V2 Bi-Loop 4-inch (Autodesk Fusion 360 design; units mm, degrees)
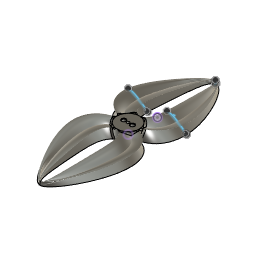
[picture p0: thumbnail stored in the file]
sketch "Hub 5mm Shaft" plane through (0, 0, 0) normal (0, 0, 1) x axis (1, 0, 0)
  circle C1 centre (0, 0) radius 6.5
  circle C2 centre (0, 0) radius 2.5
  point P1 (0, 0)
  point P2 (0, 0)
  point P3 (0, 0)
  coincident P1 P2
  coincident P1 P3
  dimension "d1" diameter C1 = 13
  dimension "d2" diameter C2 = 5
extrude "Extrude1" new body sketch "Hub 5mm Shaft" along normal blind 6 bodies "Hub 5mm Shaft"
sketch "Start Profile" plane through (0, 0, 0) normal (1, 0, 0) x axis (0, 1, 0)
  line L1 (-0.9, 0) -> (0, 0)
  line L2 (-5, 0) -> (-5.9, 0)
  curve K1 (-5, 0) -> (-5.9, 0)
  curve K2 (0, 0) -> (-0.9, 0)
  curve K3 (6.3, 6) -> (5.7, 6)
  curve K4 (0.3, 6) -> (-0.3, 6)
  curve K5 (-1, -1.5) -> (1, 1.5)
  curve K6 (-6, -1.5) -> (-4, 1.5)
  curve K7 (-4.9, 1.5) -> (-6.9, -1.5)
  curve K8 (0.1, 1.5) -> (-1.9, -1.5)
  point P1 (0, 0)
  point P2 (0, 0)
  point P6 (0, 0)
  point P3 (6, 6)
  point P4 (0, 6)
  point P8 (-5, 0)
  point P5 (-5.9, 0)
  point P7 (-0.9, 0)
  point P9 (5.7, 6)
  point P10 (6.3, 6)
  point P11 (-0.3, 6)
  point P12 (0.3, 6)
  point P21 (0, 0)
  point P24 (0, 0)
  coincident P1 P2
  coincident P1 P6
  horizontal L1
  horizontal L2
  midpoint P3 K3
  midpoint P4 K4
  midpoint P2 K5
  midpoint P8 K6
  midpoint P5 K7
  midpoint P7 K8
  dimension "d5" distance P2 P7 = 0.9
  dimension "d6" distance P5 P8 = 0.9
  dimension "d7" distance P2 P8 = 5
  dimension "d8" distance P4 P5 = 5.9
  dimension "d9" distance P2 P4 = 6
  dimension "d10" distance P2 P3 = 6
  dimension "d11" distance P2 P3 = 6
  dimension "d12" distance P9 P10 = 0.6
  dimension "d13" distance P11 P12 = 0.6
  dimension "d17" distance P21 = 50.8 (= "( ( 101.6 ) / 2 ) * 1 mm")
  dimension "d38" distance P24 = 16.9333 (= "( 101.6 / 3 / 2 ) * 1 mm")
  dimension "d46" distance P24 = 16.9333 (= "( 101.6 / 2 / 3 ) * 1 mm")
sketch "Edge Profile" plane through (0, 0, 0) normal (1, 0, 0) x axis (0, 1, 0)
  line L1 (50, 0) -> (50.8, 0)
  curve K1 (50, 0) -> (50.8, 0)
  curve K2 (50.8, 1) -> (50.8, -1)
  curve K3 (50, -1) -> (50, 1)
  curve K4 (50.1, 2) -> (50.6, 2)
  point P2 (50.8, 0)
  point P3 (50, 0)
  point P4 (50.35, 2)
  point P9 (0, 0)
  point P10 (50.6, 2)
  point P11 (50.1, 2)
  horizontal L1
  midpoint P2 K2
  midpoint P3 K3
  midpoint P4 K4
  dimension "d14" distance P2 P3 = 0.8
  dimension "d15" distance P2 P4 = 2
  dimension "d16" distance P2 P4 = 0.45
  dimension "d17" distance P2 P9 = 50.8 (= "( ( 101.6 ) / 2 ) * 1 mm")
  dimension "d18" distance P10 P11 = 0.5
sketch "Target Rail" plane through (0, 0, 0) normal (0, 0, 1) x axis (1, 0, 0)
  line L1 (0, -0.9) -> (0, 0)
  line L2 (0, 21.1667) -> (0, 0)
  line L3 (21.1667, 21.1667) -> (0, 21.1667)
  line L4 (-21.1667, 21.1667) -> (0, 21.1667)
  circle C1 centre (0, 0) radius 63.5
  point P1 (0, 0)
  point P2 (0, 0)
  point P5 (0, 0)
  point P6 (0, 21.1667)
  point P7 (21.1667, 21.1667)
  point P8 (-21.1667, 21.1667)
  coincident P1 P2
  coincident P1 P5
  parallel L1 L2
  perpendicular L2 L3
  perpendicular L2 L4
  dimension "d19" diameter C1 = 127
  dimension "d20" distance P5 P6 = 21.1667 (= "( ( 127 / 2 ) / 3 ) * 1 mm")
  dimension "d21" distance P6 P7 = 21.1667 (= "( ( 127 / 2 ) / 3 ) * 1 mm")
  dimension "d22" distance P6 P8 = 21.1667 (= "( 127 / 2 / 3 ) * 1 mm")
work_plane "WorkPlane1" AlongDistance 16.9333 (= "( 101.6 / 2 / 3 ) * 1 mm")
sketch "Mid Profile" plane through (0, 16.9333, 0) normal (0, 1, 0) x axis (1, 0, 0)
  curve K1 (16.0333, 0) -> (16.9333, 0)
  curve K2 (14.2667, -2) -> (19.6, 2)
  curve K3 (5.1333, -6) -> (5.7333, -6)
  curve K4 (18.9, 2) -> (13.1667, -2)
  line L1 (16.0333, 0) -> (16.9333, 0)
  line L2 (5.1333, -6) -> (5.7333, -6)
  line L3 (-6.3333, 0) -> (-5.4333, 0)
  curve K5 (-6.3333, 0) -> (-5.4333, 0)
  curve K6 (-8.1, -2) -> (-2.7667, 2)
  curve K7 (-17.2333, -6) -> (-16.6333, -6)
  curve K8 (-3.4667, 2) -> (-9.2, -2)
  point P2 (0, 0)
  point P5 (16.9333, 0)
  point P7 (5.4333, -6)
  point P3 (5.7333, -6)
  point P4 (5.1333, -6)
  point P14 (-16.9333, -6)
  point P17 (-5.4333, 0)
  point P13 (-16.6333, -6)
  point P18 (-17.2333, -6)
  point P19 (-6.3333, 0)
  point P8 (16.0333, 0)
  dimension "d38" distance P2 P5 = 16.9333 (= "( 101.6 / 3 / 2 ) * 1 mm")
  dimension "d39" distance P5 P7 = 11.5
  dimension "d40" distance P5 P7 = 6
  dimension "d41" distance P3 P4 = 0.6
  dimension "d42" distance P14 P17 = 11.5
  dimension "d43" distance P14 P17 = 6
  dimension "d44" distance P13 P18 = 0.6
  dimension "d46" distance P2 P14 = 16.9333 (= "( 101.6 / 2 / 3 ) * 1 mm")
  dimension "d47" distance P17 P19 = 0.9
  dimension "d84" distance P5 P8 = 0.9
sketch "End Profile" plane through (0, 0, 0) normal (1, 0, 0) x axis (0, 1, 0)
  line L1 (5, 0) -> (5.8, 0)
  curve K1 (0, 0) -> (0.8, 0)
  curve K2 (-0.2, 1.5) -> (1.8, -1.5)
  curve K3 (-6.25, 6) -> (-5.75, 6)
  curve K4 (1, -1.5) -> (-1, 1.5)
  line L2 (0.8, 0) -> (0, 0)
  curve K5 (5, 0) -> (5.8, 0)
  curve K6 (4.8, 1.5) -> (6.8, -1.5)
  curve K7 (-0.25, 6) -> (0.35, 6)
  curve K8 (6, -1.5) -> (4, 1.5)
  line L3 (-6.25, 6) -> (-5.75, 6)
  line L4 (-0.25, 6) -> (0.35, 6)
  point P2 (0, 0)
  point P11 (0.8, 0)
  point P14 (5, 0)
  point P20 (5.8, 0)
  point P5 (0, 0)
  point P6 (0, 6)
  point P12 (0, 0)
  point P18 (-6, 6)
  point P7 (-6.25, 6)
  point P23 (-5.75, 6)
  point P3 (0.35, 6)
  point P17 (-0.25, 6)
  dimension "d57" distance P2 P11 = 0.8
  dimension "d58" distance P14 P20 = 0.8
  dimension "d59" distance P5 P20 = 5.8
  dimension "d60" distance P6 P12 = 6
  dimension "d61" distance P6 P20 = 5.8
  dimension "d62" distance P11 P18 = 6.8
  dimension "d63" distance P2 P7 = 6
  dimension "d65" distance P7 P23 = 0.5
  dimension "d66" distance P3 P17 = 0.6
  dimension "d67" distance P6 P17 = 0.25
sketch "Lower Rails" plane through (0, 0, 0) normal (0, 0, 1) x axis (1, 0, 0)
  curve K1 (0, 5) -> (0, -0.9)
  curve K2 (0, 0) -> (0, 5.8)
  curve K3 (-9, 0) -> (9, 0)
  curve K4 (9, -1.1) -> (-9, -0.7)
  curve K5 (-3, 5.8) -> (3, 5.8)
  curve K6 (3, 5) -> (-3, 5)
  curve K7 (-5.5871, 26.9005) -> (-5.2796, 6.9661)
  curve K8 (-6.1796, 6.9661) -> (-6.4871, 26.9005)
  curve K9 (-2.5, 50.8) -> (2.5, 50.8)
  curve K10 (2.2, 50) -> (-2.2, 50)
  point P2 (0, -0.9)
  point P7 (0, -0.9)
  point P3 (16.9333, 16.9333)
  point P8 (16.9333, 16.9333)
  point P4 (0, 50.8)
  point P9 (0, 50.8)
  point P5 (-6.3333, 16.9333)
  point P10 (-6.3333, 16.9333)
  point P11 (0, 5.8)
  point P16 (0, 5.8)
  point P12 (-5.4333, 16.9333)
  point P17 (-5.4333, 16.9333)
  point P13 (0, 50)
  point P18 (0, 50)
  point P14 (16.0333, 16.9333)
  point P19 (16.0333, 16.9333)
  point P1 (0, 0)
  point P15 (0, 0)
  point P6 (0, 5)
  coincident P2 P7
  coincident P3 P8
  coincident P4 P9
  coincident P5 P10
  coincident P11 P16
  coincident P12 P17
  coincident P13 P18
  coincident P14 P19
  coincident P1 P15
  midpoint P15 K3
  midpoint P2 K4
  midpoint P11 K5
  midpoint P6 K6
  midpoint P12 K7
  midpoint P5 K8
  parallel K7 K8
  midpoint P4 K9
  midpoint P13 K10
work_plane "WorkPlane2" AlongDistance 6
sketch "Upper Rails" plane through (0, 0, 6) normal (0, 0, 1) x axis (1, 0, 0)
  curve K1 (0, 0) -> (0, 6)
  curve K2 (9.5, -0.3) -> (-9.5, 0.3)
  curve K3 (3, 6) -> (-3, 6)
  curve K4 (5.4985, 26.7287) -> (5.3682, 7.138)
  curve K5 (-17.3406, 8.5207) -> (-16.5261, 25.3459)
  curve K6 (-1.8, 50.35) -> (1.8, 50.35)
  point P2 (0, 6)
  point P7 (0, 6)
  point P3 (5.4333, 16.9333)
  point P8 (5.4333, 16.9333)
  point P5 (-16.9333, 16.9333)
  point P10 (-16.9333, 16.9333)
  point P6 (0, 0)
  point P4 (0, 50.35)
  coincident P2 P7
  coincident P3 P8
  coincident P5 P10
  midpoint P6 K2
  midpoint P2 K3
  midpoint P3 K4
  midpoint P5 K5
  midpoint P4 K6
loft "Loft1" sketch "Start Profile" + "Mid Profile" + "Edge Profile" bodies "Template 1 4x2.5x2"
loft "Loft2" sketch "Edge Profile" + "Mid Profile" + "End Profile"
circular_pattern "C-Pattern1" TotalAngle 360 bodies "Template 2 4x2.5x2"
sketch "Blade Trimmer" plane through (0, 0, 0) normal (0, 0, 1) x axis (1, 0, 0)
  circle C1 centre (0, 0) radius 3
  point P1 (0, 0)
  point P2 (0, 0)
  coincident P1 P2
  dimension "d71" diameter C1 = 6
extrude "Extrude2" cut sketch "Blade Trimmer" along normal blind 14
copy_paste_bodies "CopyPasteBodies1"
chamfer "Start Profile" distance 0.5
offset_faces "OffsetFaces1" distance 2
combine "Start Profile"
fillet "Fillet1" radius 1
offset_faces "OffsetFaces2" distance -2
sketch "Fillet Trimmer" plane through (0, 0, 6) normal (0, 0, 1) x axis (-1, 0, 0)
  arc A1 centre (0, 0) radius 6.5 clockwise from (6.5, -0.0086) to (5.4558, -3.5333)
  arc A2 centre (0, 0) radius 6.5 clockwise from (0.6602, 6.4664) to (4.9682, 4.1913)
  arc A3 centre (0, 0) radius 6.5 clockwise from (-6.5, 0.0086) to (-5.4558, 3.5333)
  arc A4 centre (0, 0) radius 6.5 clockwise from (-4.9682, -4.1913) to (-6.5, 0.0086)
  arc A5 centre (0, 0) radius 6.5 clockwise from (-0.6602, -6.4664) to (-4.9682, -4.1913)
  arc A6 centre (0, 0) radius 6.5 clockwise from (5.4558, -3.5333) to (-0.6602, -6.4664)
  circle C1 centre (0, 0) radius 3
  circle C2 centre (0, 0) radius 7.5
  arc A7 centre (0, 0) radius 6.5 clockwise from (4.9682, 4.1913) to (6.5, -0.0086)
  arc A8 centre (0, 0) radius 6.5 clockwise from (-5.4558, 3.5333) to (0.6602, 6.4664)
  point P1 (0, 0)
  point P10 (0, 0)
  coincident P1 P10
  dimension "d79" diameter C2 = 15
extrude "Extrude3" cut sketch "Fillet Trimmer" profile of A1 A2 A3 A4 A5 A6 C1 C2 along normal blind 5
mirror "Mirror1" mirrorStitchTolerance 0.1 bodies "4x2.5x2 CW"
copy_paste_bodies "CopyPasteBodies2"
move "Move1"
sketch "Sketch14" plane through (0, 0, 6) normal (0, 0, 1) x axis (-1, 0, 0)
  curve K1 (4.9682, 4.1913) -> (3.2451, 6.7616)
  curve K2 (2.1589, 7.1825) -> (1.5502, 6.7475)
  curve K3 (1.5502, 6.7475) -> (0.6602, 6.4664)
  curve K4 (-5.4558, 3.5333) -> (-7.2679, 1.8514)
  curve K5 (-7.4265, 1.0471) -> (-7.1853, 0.9613)
  curve K6 (-7.1853, 0.9613) -> (-6.5, 0.0086)
  curve K7 (-4.9682, -4.1913) -> (-3.2451, -6.7616)
  curve K8 (-2.1589, -7.1825) -> (-1.5502, -6.7475)
  curve K9 (-1.5502, -6.7475) -> (-0.6602, -6.4664)
  curve K10 (5.4558, -3.5333) -> (7.2679, -1.8514)
  curve K11 (7.4265, -1.0471) -> (7.1853, -0.9613)
  curve K12 (7.1853, -0.9613) -> (6.5, -0.0086)
  arc A1 centre (0, 0) radius 6.5 clockwise from (4.9682, 4.1913) to (6.5, -0.0086)
  arc A2 centre (0, 0) radius 7.5 clockwise from (2.1589, 7.1825) to (3.2451, 6.7616)
  arc A3 centre (0, 0) radius 6.5 clockwise from (-5.4558, 3.5333) to (0.6602, 6.4664)
  arc A4 centre (0, 0) radius 7.5 clockwise from (-7.4265, 1.0471) to (-7.2679, 1.8514)
  arc A5 centre (0, 0) radius 6.5 clockwise from (-4.9682, -4.1913) to (-6.5, 0.0086)
  arc A6 centre (0, 0) radius 7.5 clockwise from (-2.1589, -7.1825) to (-3.2451, -6.7616)
  arc A7 centre (0, 0) radius 6.5 clockwise from (5.4558, -3.5333) to (-0.6602, -6.4664)
  arc A8 centre (0, 0) radius 7.5 clockwise from (7.4265, -1.0471) to (7.2679, -1.8514)
  circle C1 centre (0, 0) radius 3
extrude "Extrude4" add sketch "Sketch14" profile of C1 against normal blind 6
sketch "Sketch15" plane through (0, 0, 6) normal (0, 0, 1) x axis (-1, 0, 0)
  curve K1 (4.9682, 4.1913) -> (3.2451, 6.7616)
  curve K2 (2.1589, 7.1825) -> (1.5502, 6.7475)
  curve K3 (1.5502, 6.7475) -> (0.6602, 6.4664)
  curve K4 (-5.4558, 3.5333) -> (-7.2679, 1.8514)
  curve K5 (-7.4265, 1.0471) -> (-7.1853, 0.9613)
  curve K6 (-7.1853, 0.9613) -> (-6.5, 0.0086)
  curve K7 (-4.9682, -4.1913) -> (-3.2451, -6.7616)
  curve K8 (-2.1589, -7.1825) -> (-1.5502, -6.7475)
  curve K9 (-1.5502, -6.7475) -> (-0.6602, -6.4664)
  curve K10 (5.4558, -3.5333) -> (7.2679, -1.8514)
  curve K11 (7.4265, -1.0471) -> (7.1853, -0.9613)
  curve K12 (7.1853, -0.9613) -> (6.5, -0.0086)
  arc A1 centre (0, 0) radius 6.5 clockwise from (4.9682, 4.1913) to (6.5, -0.0086)
  arc A2 centre (0, 0) radius 7.5 clockwise from (2.1589, 7.1825) to (3.2451, 6.7616)
  arc A3 centre (0, 0) radius 6.5 clockwise from (-5.4558, 3.5333) to (0.6602, 6.4664)
  arc A4 centre (0, 0) radius 7.5 clockwise from (-7.4265, 1.0471) to (-7.2679, 1.8514)
  arc A5 centre (0, 0) radius 6.5 clockwise from (-4.9682, -4.1913) to (-6.5, 0.0086)
  arc A6 centre (0, 0) radius 7.5 clockwise from (-2.1589, -7.1825) to (-3.2451, -6.7616)
  arc A7 centre (0, 0) radius 6.5 clockwise from (5.4558, -3.5333) to (-0.6602, -6.4664)
  arc A8 centre (0, 0) radius 7.5 clockwise from (7.4265, -1.0471) to (7.2679, -1.8514)
  circle C1 centre (0, 0) radius 0.8
  circle C2 centre (-2.5, 0) radius 1.05
  circle C3 centre (2.5, 0) radius 1.05
  point P1 (0, 0)
  point P23 (0, 0)
  point P25 (2.5, 0)
  point P24 (-2.5, 0)
  coincident P1 P23
  dimension "d96" diameter C1 = 1.6
  dimension "d97" diameter C2 = 2.1
  dimension "d98" diameter C3 = 2.1
  dimension "d99" distance P23 P25 = 2.5
  dimension "d100" distance P1 P24 = 2.5
extrude "Extrude5" cut sketch "Sketch15" profile of C1 C2 C3 against normal blind 11
chamfer "Start Profile" distance 0.25
mirror "Mirror2" mirrorStitchTolerance 0.1 bodies "4x2.5x2T CW"
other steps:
base_feature "Base Feature1" bodies "Hub 5mm Shaft", "4x2.5x2 CCW"
base_feature "Base Feature2" bodies "4x2.5x2 CCW", "4x2.5x2T CCW"
named bodies: "Hub 5mm Shaft", "Template 1 4x2.5x2", "Template 2 4x2.5x2", "4x2.5x2 CCW", "4x2.5x2 CW", "4x2.5x2T CCW", "4x2.5x2T CW"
